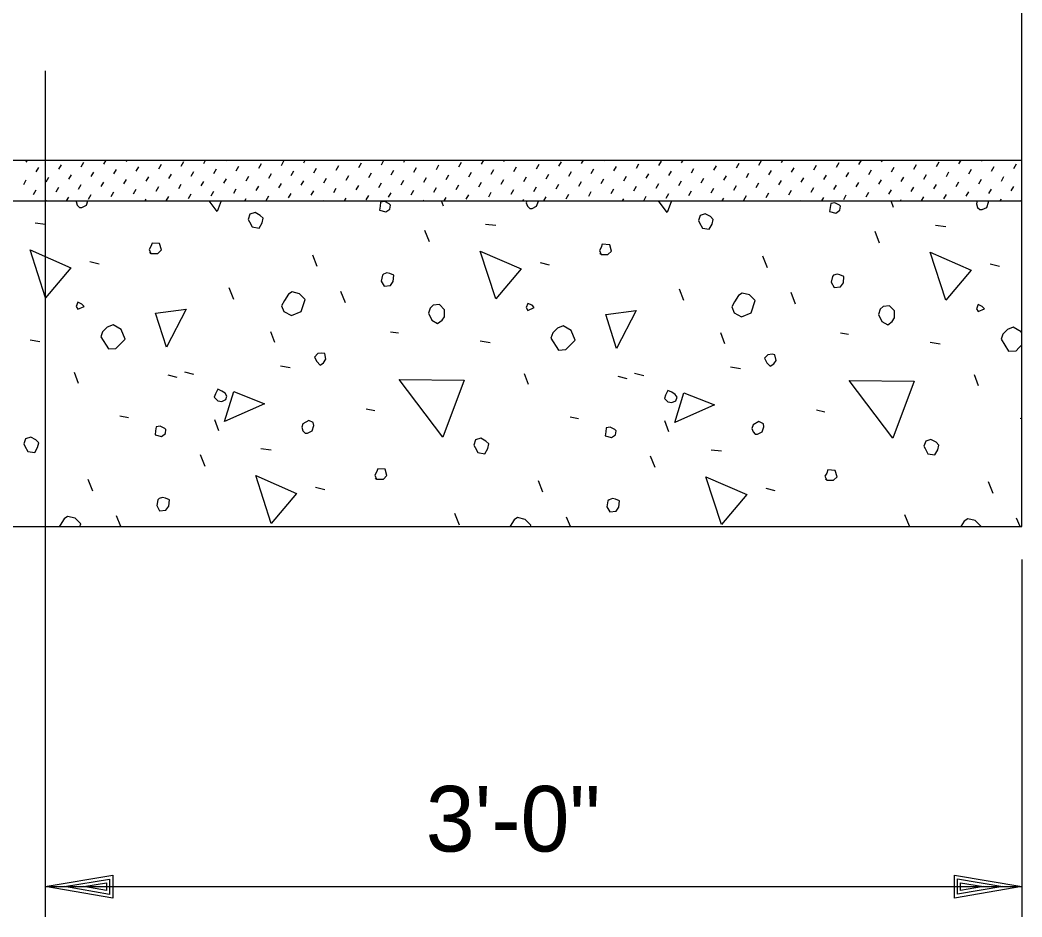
# Model space of a CAD drawing. Extents: x 0 to 40.8, y 1 to 28.
# Drawn here: x 36.479 to 39.557, y 8.831 to 11.585 of the extents above; entities that cross this region are included whole.
import ezdxf

# ---------------------------------------------------------------- set-up
doc = ezdxf.new("R2010")
doc.units = 0
for name, color, linetype in [('Dimension', 7, 'Continuous'), ('Miscellaneous', 7, 'Continuous'), ('TextStructures', 7, 'Continuous'), ('TrafBarrierConc', 7, 'Continuous')]:
    doc.layers.add(name, color=color, linetype=linetype)

# ---------------------------------------------------------------- blocks, each defined once
blk = doc.blocks.new('ALT')
at = {"layer": 'Dimension'}
for points in [[(0, 0), (-0.0006332, -0.000105), (-0.0006332, 0.000105)], [(-0.0001804, 0), (-0.0006037, -0.0000689), (-0.0006037, 0.0000722)], [(-0.0003609, 0), (-0.0005741, -0.0000361), (-0.0005741, 0.0000361)]]:
    blk.add_lwpolyline(points, close=True, dxfattribs=at)

msp = doc.modelspace()

# ---------------------------------------------------------------- linework, layer by layer
at = {"layer": 'Dimension'}
for p, q in [((36.5565, 11.4287), (36.5565, 8.8308)), ((39.5565, 9.9287), (39.5565, 8.8308)), ((39.5565, 8.9237), (36.5565, 8.9237))]:
    msp.add_line(p, q, dxfattribs=at)
at = {"layer": 'Miscellaneous'}
for p, q in [((36.4986, 11.1491), (36.5017, 11.1545)), ((36.5983, 11.1267), (36.6064, 11.1407)), ((36.6674, 11.1348), (36.6756, 11.1488)), ((36.7366, 11.1429), (36.7433, 11.1545)), ((36.8058, 11.151), (36.8078, 11.1545)), ((36.9055, 11.1286), (36.9136, 11.1426)), ((36.9746, 11.1367), (36.9827, 11.1507)), ((37.0438, 11.1448), (37.0494, 11.1545)), ((37.113, 11.1529), (37.1139, 11.1545)), ((37.2127, 11.1305), (37.2208, 11.1444)), ((37.2818, 11.1386), (37.2899, 11.1526)), ((37.351, 11.1467), (37.3555, 11.1545)), ((37.5198, 11.1323), (37.5279, 11.1463)), ((37.589, 11.1404), (37.5971, 11.1544)), ((37.6582, 11.1485), (37.6616, 11.1545)), ((37.7579, 11.1261), (37.766, 11.1401)), ((37.827, 11.1342), (37.8351, 11.1482)), ((37.8962, 11.1423), (37.9033, 11.1545)), ((37.9654, 11.1504), (37.9677, 11.1545)), ((38.0651, 11.128), (38.0732, 11.142)), ((38.1342, 11.1361), (38.1423, 11.1501)), ((38.2034, 11.1442), (38.2094, 11.1545)), ((38.2725, 11.1523), (38.2738, 11.1545)), ((38.3722, 11.1299), (38.3803, 11.1439)), ((38.4414, 11.138), (38.4495, 11.152)), ((38.5106, 11.1461), (38.5155, 11.1545)), ((38.5797, 11.1542), (38.5799, 11.1545)), ((38.6794, 11.1317), (38.6875, 11.1457)), ((38.7486, 11.1398), (38.7567, 11.1538)), ((38.8178, 11.1479), (38.8216, 11.1545)), ((38.9866, 11.1336), (38.9947, 11.1476)), ((39.0558, 11.1417), (39.0632, 11.1545)), ((39.1249, 11.1498), (39.1277, 11.1545)), ((39.2246, 11.1274), (39.2327, 11.1414)), ((39.2938, 11.1355), (39.3019, 11.1495)), ((39.363, 11.1436), (39.3693, 11.1545)), ((39.4321, 11.1517), (39.4338, 11.1545)), ((39.5318, 11.1293), (39.5399, 11.1433)), ((36.5291, 11.1186), (36.5372, 11.1326)), ((36.6288, 11.0962), (36.6369, 11.1102)), ((36.698, 11.1043), (36.7061, 11.1183)), ((36.7671, 11.1124), (36.7752, 11.1264)), ((36.8363, 11.1205), (36.8444, 11.1345)), ((36.936, 11.098), (36.9441, 11.112)), ((37.0052, 11.1061), (37.0133, 11.1201)), ((37.0743, 11.1142), (37.0824, 11.1282)), ((37.1435, 11.1224), (37.1516, 11.1363)), ((37.2432, 11.0999), (37.2513, 11.1139)), ((37.3124, 11.108), (37.3205, 11.122)), ((37.3815, 11.1161), (37.3896, 11.1301)), ((37.4507, 11.1242), (37.4588, 11.1382)), ((37.5504, 11.1018), (37.5585, 11.1158)), ((37.6195, 11.1099), (37.6276, 11.1239)), ((37.6887, 11.118), (37.6968, 11.132)), ((37.7884, 11.0956), (37.7965, 11.1096)), ((37.8576, 11.1037), (37.8657, 11.1177)), ((37.9267, 11.1118), (37.9348, 11.1258)), ((37.9959, 11.1199), (38.004, 11.1339)), ((38.0956, 11.0975), (38.1037, 11.1115)), ((38.1647, 11.1056), (38.1728, 11.1196)), ((38.2339, 11.1137), (38.242, 11.1277)), ((38.3031, 11.1218), (38.3112, 11.1358)), ((38.4028, 11.0993), (38.4109, 11.1133)), ((38.4719, 11.1074), (38.48, 11.1214)), ((38.5411, 11.1155), (38.5492, 11.1295)), ((38.6103, 11.1236), (38.6184, 11.1376)), ((38.71, 11.1012), (38.7181, 11.1152)), ((38.7791, 11.1093), (38.7872, 11.1233)), ((38.8483, 11.1174), (38.8564, 11.1314)), ((38.9174, 11.1255), (38.9256, 11.1395)), ((38.948, 11.095), (38.9561, 11.109)), ((39.0171, 11.1031), (39.0252, 11.1171)), ((39.0863, 11.1112), (39.0944, 11.1252)), ((39.1555, 11.1193), (39.1636, 11.1333)), ((39.2552, 11.0969), (39.2633, 11.1109)), ((39.3243, 11.105), (39.3324, 11.119)), ((39.3935, 11.1131), (39.4016, 11.1271)), ((39.4627, 11.1212), (39.4708, 11.1352)), ((36.4905, 11.08), (36.4986, 11.094)), ((36.5597, 11.0881), (36.5678, 11.1021)), ((36.6593, 11.0656), (36.6674, 11.0796)), ((36.7285, 11.0737), (36.7366, 11.0877)), ((36.7977, 11.0818), (36.8058, 11.0958)), ((36.8668, 11.0899), (36.8749, 11.1039)), ((36.9665, 11.0675), (36.9746, 11.0815)), ((37.0357, 11.0756), (37.0438, 11.0896)), ((37.1049, 11.0837), (37.113, 11.0977)), ((37.174, 11.0918), (37.1821, 11.1058)), ((37.2737, 11.0694), (37.2818, 11.0834)), ((37.3429, 11.0775), (37.351, 11.0915)), ((37.412, 11.0856), (37.4201, 11.0996)), ((37.4812, 11.0937), (37.4893, 11.1077)), ((37.5809, 11.0713), (37.589, 11.0853)), ((37.6501, 11.0794), (37.6582, 11.0934)), ((37.7192, 11.0875), (37.7273, 11.1015)), ((37.8189, 11.065), (37.827, 11.079)), ((37.8881, 11.0731), (37.8962, 11.0871)), ((37.9573, 11.0813), (37.9654, 11.0952)), ((38.0264, 11.0894), (38.0345, 11.1033)), ((38.1261, 11.0669), (38.1342, 11.0809)), ((38.1953, 11.075), (38.2034, 11.089)), ((38.2644, 11.0831), (38.2725, 11.0971)), ((38.3336, 11.0912), (38.3417, 11.1052)), ((38.4333, 11.0688), (38.4414, 11.0828)), ((38.5025, 11.0769), (38.5106, 11.0909)), ((38.5716, 11.085), (38.5797, 11.099)), ((38.6408, 11.0931), (38.6489, 11.1071)), ((38.7405, 11.0707), (38.7486, 11.0847)), ((38.8097, 11.0788), (38.8178, 11.0928)), ((38.8788, 11.0869), (38.8869, 11.1009)), ((38.9785, 11.0645), (38.9866, 11.0785)), ((39.0477, 11.0726), (39.0558, 11.0866)), ((39.1168, 11.0807), (39.1249, 11.0947)), ((39.186, 11.0888), (39.1941, 11.1028)), ((39.2857, 11.0663), (39.2938, 11.0803)), ((39.3549, 11.0744), (39.363, 11.0884)), ((39.424, 11.0825), (39.4321, 11.0965)), ((39.4932, 11.0906), (39.5013, 11.1046)), ((36.521, 11.0494), (36.5291, 11.0634)), ((36.5902, 11.0575), (36.5983, 11.0715)), ((36.6899, 11.0351), (36.698, 11.0491)), ((36.759, 11.0432), (36.7671, 11.0572)), ((36.8282, 11.0513), (36.8363, 11.0653)), ((36.8974, 11.0594), (36.9055, 11.0734)), ((36.9971, 11.037), (37.0052, 11.051)), ((37.0662, 11.0451), (37.0743, 11.0591)), ((37.1354, 11.0532), (37.1435, 11.0672)), ((37.2046, 11.0613), (37.2127, 11.0753)), ((37.3043, 11.0389), (37.3124, 11.0529)), ((37.3734, 11.047), (37.3815, 11.061)), ((37.4426, 11.0551), (37.4507, 11.0691)), ((37.5117, 11.0632), (37.5198, 11.0772)), ((37.6114, 11.0407), (37.6195, 11.0547)), ((37.6806, 11.0488), (37.6887, 11.0628)), ((37.7498, 11.0569), (37.7579, 11.0709)), ((37.8495, 11.0345), (37.8576, 11.0485)), ((37.9186, 11.0426), (37.9267, 11.0566)), ((37.9878, 11.0507), (37.9959, 11.0647)), ((38.057, 11.0588), (38.0651, 11.0728)), ((38.1566, 11.0364), (38.1647, 11.0504)), ((38.2258, 11.0445), (38.2339, 11.0585)), ((38.295, 11.0526), (38.3031, 11.0666)), ((38.3641, 11.0607), (38.3722, 11.0747)), ((38.4638, 11.0383), (38.4719, 11.0523)), ((38.533, 11.0464), (38.5411, 11.0604)), ((38.6022, 11.0545), (38.6103, 11.0685)), ((38.6713, 11.0626), (38.6794, 11.0766)), ((38.771, 11.0402), (38.7791, 11.0541)), ((38.8402, 11.0483), (38.8483, 11.0622)), ((38.9093, 11.0564), (38.9174, 11.0704)), ((39.009, 11.0339), (39.0171, 11.0479)), ((39.0782, 11.042), (39.0863, 11.056)), ((39.1474, 11.0501), (39.1555, 11.0641)), ((39.2165, 11.0582), (39.2246, 11.0722)), ((39.3162, 11.0358), (39.3243, 11.0498)), ((39.3854, 11.0439), (39.3935, 11.0579)), ((39.4546, 11.052), (39.4627, 11.066)), ((39.5237, 11.0601), (39.5318, 11.0741)), ((36.5577, 11.0295), (36.5597, 11.0329)), ((36.6222, 11.0295), (36.6288, 11.041)), ((36.8638, 11.0295), (36.8668, 11.0348)), ((36.9283, 11.0295), (36.936, 11.0429)), ((37.1699, 11.0295), (37.174, 11.0367)), ((37.2351, 11.0308), (37.2432, 11.0448)), ((37.4115, 11.0295), (37.412, 11.0304)), ((37.476, 11.0295), (37.4812, 11.0385)), ((37.5423, 11.0326), (37.5504, 11.0466)), ((37.7176, 11.0295), (37.7192, 11.0323)), ((37.7795, 11.0134), (37.7735, 11.0295)), ((37.7821, 11.0295), (37.7884, 11.0404)), ((38.0237, 11.0295), (38.0264, 11.0342)), ((38.0882, 11.0295), (38.0956, 11.0423)), ((38.3298, 11.0295), (38.3336, 11.0361)), ((38.3947, 11.0302), (38.4028, 11.0442)), ((38.5714, 11.0295), (38.5716, 11.0298)), ((38.6359, 11.0295), (38.6408, 11.0379)), ((38.7019, 11.032), (38.71, 11.046)), ((38.8775, 11.0295), (38.8788, 11.0317)), ((38.942, 11.0295), (38.948, 11.0398)), ((39.1619, 11.0099), (39.1546, 11.0295)), ((39.1836, 11.0295), (39.186, 11.0336)), ((39.2481, 11.0295), (39.2552, 11.0417)), ((39.4897, 11.0295), (39.4932, 11.0355)), ((39.5542, 11.0296), (39.5565, 11.0335)), ((36.5261, 10.9621), (36.5579, 10.9586)), ((37.9085, 10.9586), (37.9403, 10.9551)), ((39.2909, 10.9551), (39.3227, 10.9515)), ((37.737, 10.9038), (37.7229, 10.9391)), ((39.1194, 10.9003), (39.1053, 10.9356)), ((37.3923, 10.8278), (37.3782, 10.8631)), ((36.6941, 10.8437), (36.7224, 10.8366)), ((38.0765, 10.8402), (38.1047, 10.8331)), ((38.7747, 10.8242), (38.7606, 10.8596)), ((39.4589, 10.8366), (39.4871, 10.8295)), ((37.136, 10.727), (37.1219, 10.7624)), ((37.479, 10.7164), (37.4648, 10.7518)), ((38.5184, 10.7235), (38.5043, 10.7588)), ((38.8613, 10.7129), (38.8472, 10.7482)), ((37.2615, 10.5944), (37.2491, 10.628)), ((37.6168, 10.628), (37.6416, 10.6245)), ((38.6439, 10.5909), (38.6315, 10.6245)), ((38.9992, 10.6245), (39.024, 10.6209)), ((36.5102, 10.6033), (36.5403, 10.598)), ((37.8926, 10.5997), (37.9227, 10.5944)), ((39.275, 10.5962), (39.3051, 10.5909)), ((36.6587, 10.4689), (36.6463, 10.5025)), ((36.9327, 10.4954), (36.961, 10.4884)), ((36.984, 10.5043), (37.0123, 10.4972)), ((37.2792, 10.5237), (37.3092, 10.5184)), ((38.0411, 10.4654), (38.0287, 10.499)), ((38.3664, 10.5007), (38.3947, 10.4937)), ((38.6616, 10.5202), (38.6916, 10.5149)), ((39.4235, 10.4618), (39.4111, 10.4954)), ((38.3151, 10.4919), (38.3434, 10.4848)), ((37.5426, 10.3911), (37.5691, 10.3858)), ((38.925, 10.3876), (38.9515, 10.3823)), ((36.786, 10.3699), (36.8125, 10.3646)), ((37.09, 10.324), (37.0777, 10.3575)), ((38.1684, 10.3664), (38.1949, 10.3611)), ((38.4724, 10.3204), (38.4601, 10.354)), ((39.5508, 10.3629), (39.5565, 10.3617)), ((37.0476, 10.2144), (37.0335, 10.2497)), ((37.2191, 10.2692), (37.2509, 10.2656)), ((38.6015, 10.2656), (38.6333, 10.2621)), ((38.43, 10.2108), (38.4159, 10.2462)), ((36.7029, 10.1383), (36.6888, 10.1737)), ((38.0853, 10.1348), (38.0712, 10.1702)), ((39.4677, 10.1313), (39.4536, 10.1666)), ((37.387, 10.1507), (37.4153, 10.1437)), ((38.7694, 10.1472), (38.7977, 10.1401)), ((37.829, 10.034), (37.8148, 10.0694)), ((39.2114, 10.0305), (39.1972, 10.0659)), ((36.7885, 10.0295), (36.7754, 10.0623)), ((38.1695, 10.0295), (38.1578, 10.0588)), ((39.5505, 10.0295), (39.5402, 10.0553))]:
    msp.add_line(p, q, dxfattribs=at)
for points in [[(36.6523, 11.0295), (36.6516, 11.0275), (36.6552, 11.0169), (36.6622, 11.0099)], [(36.6622, 11.0099), (36.6693, 11.0099), (36.6835, 11.0169), (36.6877, 11.0295)], [(37.0847, 10.9975), (37.0604, 11.0295)], [(37.0967, 11.0295), (37.0847, 10.9975)], [(37.5833, 11.001), (37.6027, 10.9957), (37.6151, 11.0046), (37.6168, 11.0169), (37.6133, 11.0205), (37.5992, 11.0275), (37.5868, 11.0258), (37.585, 11.0134), (37.5833, 11.001)], [(38.0359, 11.0295), (38.034, 11.024), (38.0376, 11.0134), (38.0446, 11.0063)], [(38.0446, 11.0063), (38.0517, 11.0063), (38.0659, 11.0134), (38.0712, 11.0293), (38.0711, 11.0295)], [(38.4671, 10.9939), (38.4401, 11.0295)], [(38.4804, 11.0295), (38.4671, 10.9939)], [(38.9656, 10.9975), (38.9851, 10.9922), (38.9975, 11.001), (38.9992, 11.0134), (38.9957, 11.0169), (38.9816, 11.024), (38.9692, 11.0222), (38.9674, 11.0099), (38.9656, 10.9975)], [(39.4194, 11.0295), (39.4164, 11.0205), (39.42, 11.0099), (39.427, 11.0028)], [(39.427, 11.0028), (39.4341, 11.0028), (39.4482, 11.0099), (39.4536, 11.0258), (39.4528, 11.0295)], [(37.1837, 10.9657), (37.1926, 10.9498), (37.2138, 10.9462), (37.2226, 10.9621), (37.2262, 10.9763), (37.2173, 10.9851), (37.2014, 10.9939), (37.1855, 10.9886), (37.1802, 10.9727), (37.1837, 10.9657)], [(38.5661, 10.9621), (38.575, 10.9462), (38.5962, 10.9427), (38.605, 10.9586), (38.6086, 10.9727), (38.5997, 10.9816), (38.5838, 10.9904), (38.5679, 10.9851), (38.5626, 10.9692), (38.5661, 10.9621)], [(36.8814, 10.8684), (36.9027, 10.8684), (36.9133, 10.879), (36.908, 10.8985), (36.885, 10.9003), (36.8814, 10.8896), (36.8761, 10.8808), (36.8814, 10.8684), (36.8779, 10.872)], [(38.2638, 10.8649), (38.2851, 10.8649), (38.2957, 10.8755), (38.2904, 10.895), (38.2674, 10.8967), (38.2638, 10.8861), (38.2585, 10.8773), (38.2638, 10.8649), (38.2603, 10.8684)], [(36.5579, 10.7323), (36.5102, 10.879), (36.6357, 10.8242), (36.5579, 10.7323)], [(37.9403, 10.7288), (37.8926, 10.8755), (38.0181, 10.8207), (37.9403, 10.7288)], [(39.3227, 10.7252), (39.275, 10.872), (39.4005, 10.8172), (39.3227, 10.7252)], [(37.5886, 10.7836), (37.5974, 10.7677), (37.6168, 10.7694), (37.6257, 10.7818), (37.6274, 10.8013), (37.6151, 10.8066), (37.6062, 10.8083), (37.5956, 10.8048), (37.5921, 10.8013), (37.5886, 10.7836)], [(38.971, 10.78), (38.9798, 10.7641), (38.9992, 10.7659), (39.0081, 10.7783), (39.0098, 10.7977), (38.9975, 10.803), (38.9886, 10.8048), (38.978, 10.8013), (38.9745, 10.7977), (38.971, 10.78)], [(37.2898, 10.6899), (37.3128, 10.6775), (37.3428, 10.6899), (37.3552, 10.727), (37.3375, 10.7447), (37.3146, 10.75), (37.3039, 10.7429), (37.2916, 10.7235), (37.2827, 10.7076), (37.2898, 10.6899)], [(38.6722, 10.6864), (38.6952, 10.674), (38.7252, 10.6864), (38.7376, 10.7235), (38.7199, 10.7412), (38.6969, 10.7465), (38.6863, 10.7394), (38.674, 10.7199), (38.6651, 10.704), (38.6722, 10.6864)], [(36.6569, 10.697), (36.6764, 10.7058), (36.6693, 10.7129), (36.6569, 10.7182), (36.6516, 10.7058), (36.6569, 10.697)], [(37.7335, 10.6846), (37.7441, 10.6634), (37.7618, 10.6528), (37.7759, 10.6634), (37.783, 10.674), (37.783, 10.6952), (37.7671, 10.7111), (37.7477, 10.7093), (37.7388, 10.7005), (37.7335, 10.6846)], [(38.0393, 10.6934), (38.0588, 10.7023), (38.0517, 10.7093), (38.0393, 10.7146), (38.034, 10.7023), (38.0393, 10.6934)], [(39.4217, 10.6899), (39.4412, 10.6987), (39.4341, 10.7058), (39.4217, 10.7111), (39.4164, 10.6987), (39.4217, 10.6899)], [(36.9292, 10.5803), (36.8956, 10.6846), (36.9893, 10.697), (36.9292, 10.5803)], [(38.3116, 10.5768), (38.278, 10.6811), (38.3717, 10.6934), (38.3116, 10.5768)], [(39.1159, 10.6811), (39.1265, 10.6598), (39.1442, 10.6492), (39.1583, 10.6598), (39.1654, 10.6704), (39.1654, 10.6917), (39.1495, 10.7076), (39.13, 10.7058), (39.1212, 10.697), (39.1159, 10.6811)], [(36.7277, 10.6121), (36.7506, 10.575), (36.7736, 10.5768), (36.7825, 10.5856), (36.8019, 10.605), (36.7895, 10.6351), (36.7648, 10.6492), (36.7471, 10.6422), (36.733, 10.628), (36.7277, 10.6121)], [(38.11, 10.6086), (38.133, 10.5714), (38.156, 10.5732), (38.1648, 10.5821), (38.1843, 10.6015), (38.1719, 10.6316), (38.1472, 10.6457), (38.1295, 10.6386), (38.1154, 10.6245), (38.11, 10.6086)], [(39.5565, 10.6227), (39.5543, 10.628), (39.5296, 10.6422), (39.5119, 10.6351), (39.4977, 10.6209), (39.4924, 10.605)], [(39.4924, 10.605), (39.5154, 10.5679), (39.5384, 10.5697), (39.5472, 10.5785), (39.5565, 10.5878)], [(37.3906, 10.5361), (37.4012, 10.5255), (37.4118, 10.5326), (37.4189, 10.5432), (37.4153, 10.5608), (37.4065, 10.5626), (37.3941, 10.5608), (37.3835, 10.5502), (37.3906, 10.5361)], [(38.773, 10.5326), (38.7836, 10.522), (38.7942, 10.529), (38.8012, 10.5396), (38.7977, 10.5573), (38.7889, 10.5591), (38.7765, 10.5573), (38.7659, 10.5467), (38.773, 10.5326)], [(37.7777, 10.3045), (37.6434, 10.4813), (37.8431, 10.4795), (37.7777, 10.3045)], [(39.1601, 10.301), (39.0258, 10.4778), (39.2255, 10.476), (39.1601, 10.301)], [(37.0865, 10.4159), (37.0989, 10.4141), (37.1113, 10.4194), (37.1148, 10.43), (37.1095, 10.4389), (37.0989, 10.4459), (37.0865, 10.4512), (37.0794, 10.4371), (37.0759, 10.4265), (37.0865, 10.4159)], [(37.1077, 10.3522), (37.136, 10.4442), (37.2297, 10.407), (37.1077, 10.3522)], [(38.4689, 10.4124), (38.4813, 10.4106), (38.4937, 10.4159), (38.4972, 10.4265), (38.4919, 10.4353), (38.4813, 10.4424), (38.4689, 10.4477), (38.4618, 10.4336), (38.4583, 10.423), (38.4689, 10.4124)], [(38.4901, 10.3487), (38.5184, 10.4406), (38.6121, 10.4035), (38.4901, 10.3487)], [(37.3552, 10.3169), (37.3623, 10.3169), (37.3764, 10.324), (37.3817, 10.3399), (37.38, 10.3487), (37.3658, 10.3558), (37.3481, 10.3452), (37.3446, 10.3346), (37.3481, 10.324), (37.3552, 10.3169)], [(38.7376, 10.3134), (38.7447, 10.3134), (38.7588, 10.3204), (38.7641, 10.3363), (38.7624, 10.3452), (38.7482, 10.3522), (38.7305, 10.3416), (38.727, 10.331), (38.7305, 10.3204), (38.7376, 10.3134)], [(36.8938, 10.3116), (36.9133, 10.3063), (36.9256, 10.3151), (36.9274, 10.3275), (36.9239, 10.331), (36.9097, 10.3381), (36.8974, 10.3363), (36.8956, 10.324), (36.8938, 10.3116)], [(38.2762, 10.3081), (38.2957, 10.3027), (38.308, 10.3116), (38.3098, 10.324), (38.3063, 10.3275), (38.2921, 10.3346), (38.2798, 10.3328), (38.278, 10.3204), (38.2762, 10.3081)], [(36.4943, 10.2762), (36.5031, 10.2603), (36.5244, 10.2568), (36.5332, 10.2727), (36.5367, 10.2868), (36.5279, 10.2957), (36.512, 10.3045), (36.4961, 10.2992), (36.4908, 10.2833), (36.4943, 10.2762)], [(37.8767, 10.2727), (37.8855, 10.2568), (37.9068, 10.2533), (37.9156, 10.2692), (37.9191, 10.2833), (37.9103, 10.2921), (37.8944, 10.301), (37.8785, 10.2957), (37.8732, 10.2798), (37.8767, 10.2727)], [(39.2591, 10.2692), (39.2679, 10.2533), (39.2891, 10.2497), (39.298, 10.2656), (39.3015, 10.2798), (39.2927, 10.2886), (39.2768, 10.2974), (39.2609, 10.2921), (39.2556, 10.2762), (39.2591, 10.2692)], [(37.2509, 10.0394), (37.2032, 10.1861), (37.3287, 10.1313), (37.2509, 10.0394)], [(37.5744, 10.1755), (37.5956, 10.1755), (37.6062, 10.1861), (37.6009, 10.2055), (37.5779, 10.2073), (37.5744, 10.1967), (37.5691, 10.1878), (37.5744, 10.1755), (37.5709, 10.179)], [(38.9568, 10.1719), (38.978, 10.1719), (38.9886, 10.1825), (38.9833, 10.202), (38.9603, 10.2038), (38.9568, 10.1931), (38.9515, 10.1843), (38.9568, 10.1719), (38.9533, 10.1755)], [(38.6333, 10.0358), (38.5856, 10.1825), (38.7111, 10.1277), (38.6333, 10.0358)], [(36.8991, 10.0942), (36.908, 10.0782), (36.9274, 10.08), (36.9363, 10.0924), (36.938, 10.1118), (36.9256, 10.1171), (36.9168, 10.1189), (36.9062, 10.1154), (36.9027, 10.1118), (36.8991, 10.0942)], [(38.2815, 10.0906), (38.2904, 10.0747), (38.3098, 10.0765), (38.3186, 10.0888), (38.3204, 10.1083), (38.308, 10.1136), (38.2992, 10.1154), (38.2886, 10.1118), (38.2851, 10.1083), (38.2815, 10.0906)], [(36.6631, 10.0295), (36.6658, 10.0376), (36.6481, 10.0553), (36.6251, 10.0606), (36.6145, 10.0535), (36.6021, 10.034), (36.5996, 10.0295)], [(38.0467, 10.0295), (38.0482, 10.034), (38.0305, 10.0517), (38.0075, 10.057), (37.9969, 10.05), (37.9845, 10.0305), (37.984, 10.0295)], [(39.4302, 10.0295), (39.4306, 10.0305), (39.4129, 10.0482), (39.3899, 10.0535), (39.3793, 10.0464), (39.3685, 10.0295)]]:
    msp.add_lwpolyline(points, dxfattribs=at)
at = {"layer": 'TrafBarrierConc'}
for p, q in [((39.5565, 10.0295), (39.5565, 14.318)), ((23.7254, 11.1545), (39.5565, 11.1545)), ((23.7254, 11.0295), (39.5565, 11.0295)), ((23.7254, 10.0295), (39.5565, 10.0295))]:
    msp.add_line(p, q, dxfattribs=at)

# ---------------------------------------------------------------- block references
at = {"layer": 'Dimension', "xscale": 327.94624352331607, "yscale": 336.103515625, "rotation": 180}
msp.add_blockref('ALT', (36.5565, 8.9238), dxfattribs=at)
at = {"layer": 'Dimension', "xscale": 327.94624352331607, "yscale": 336.103515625}
msp.add_blockref('ALT', (39.5565, 8.9238), dxfattribs=at)

# ---------------------------------------------------------------- texts
at = {"layer": 'TextStructures'}
msp.add_text('3\'-0"', height=0.2016, dxfattribs=at).set_placement((37.7255, 9.0316))

doc.saveas('drawing.dxf')
